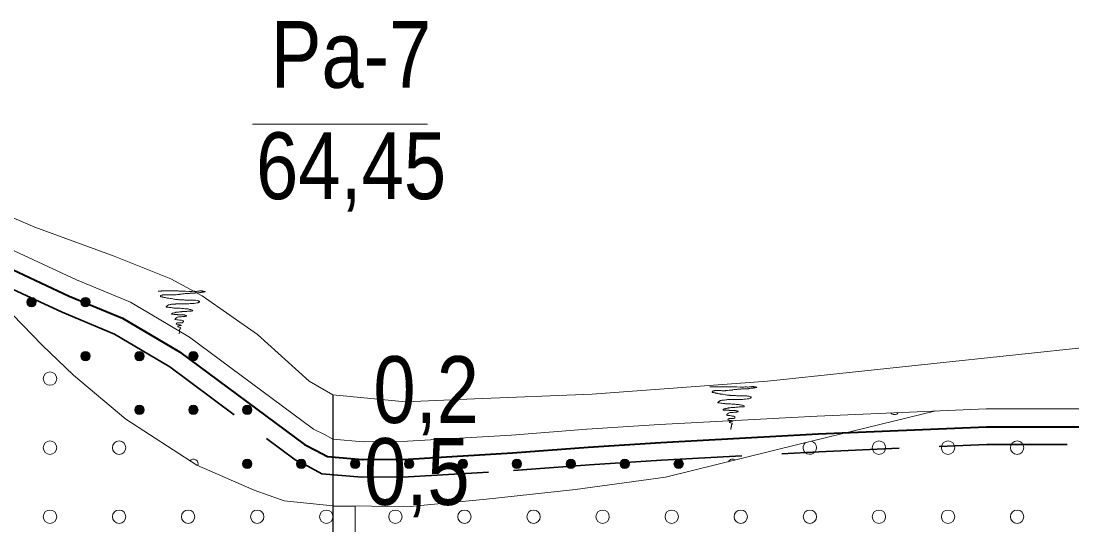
# Model space of a CAD drawing. Extents: x 640121 to 640955, y 6441885 to 6442246.
# Drawn here: x 640771.79 to 640818.96, y 6442150.81 to 6442173.44 of the extents above; entities that cross this region are included whole.
import ezdxf
from ezdxf.enums import TextEntityAlignment as Align

# ---------------------------------------------------------------- set-up
doc = ezdxf.new("R2010")
doc.units = 0
doc.header["$LTSCALE"] = 1.2
doc.linetypes.add('MEDIUM_DASHED', pattern=[4.5, 3, -1.5])
for name, color, linetype, lineweight in [('31', 7, 'Continuous', 13), ('32', 7, 'Continuous', 13), ('33', 7, 'Continuous', 13), ('35', 7, 'Continuous', 35), ('40', 7, 'Continuous', 13), ('43', 7, 'Continuous', 13), ('45', 7, 'Continuous', 13)]:
    doc.layers.add(name, color=color, linetype=linetype, lineweight=lineweight)

msp = doc.modelspace()

# ---------------------------------------------------------------- hatches: boundary and pattern name
at = {"layer": '45'}
for points in [[(640772.477, 6442160.814, 1), (640772.057, 6442160.814, 1)], [(640774.897, 6442160.814, 1), (640774.477, 6442160.814, 1)], [(640774.897, 6442158.394, 1), (640774.477, 6442158.394, 1)], [(640777.317, 6442158.394, 1), (640776.897, 6442158.394, 1)], [(640779.737, 6442158.394, 1), (640779.317, 6442158.394, 1)], [(640777.317, 6442155.974, 1), (640776.897, 6442155.974, 1)], [(640779.737, 6442155.974, 1), (640779.317, 6442155.974, 1)], [(640782.157, 6442155.974, 1), (640781.737, 6442155.974, 1)], [(640782.157, 6442153.554, 1), (640781.737, 6442153.554, 1)], [(640784.577, 6442153.554, 1), (640784.157, 6442153.554, 1)], [(640786.997, 6442153.554, 1), (640786.577, 6442153.554, 1)], [(640789.417, 6442153.554, 1), (640788.997, 6442153.554, 1)], [(640791.837, 6442153.554, 1), (640791.417, 6442153.554, 1)], [(640794.257, 6442153.554, 1), (640793.837, 6442153.554, 1)], [(640796.677, 6442153.554, 1), (640796.257, 6442153.554, 1)], [(640799.097, 6442153.554, 1), (640798.677, 6442153.554, 1)], [(640801.517, 6442153.554, 1), (640801.097, 6442153.554, 1)]]:
    msp.add_hatch(color=256, dxfattribs=at).paths.add_polyline_path(points)

# ---------------------------------------------------------------- linework, layer by layer
at = {"layer": '31'}
for points in [[(640766.27, 6442166.81), (640772.42, 6442164.18), (640775.97, 6442162.88), (640778.51, 6442161.86), (640779.92, 6442161.1), (640782.4, 6442159.37), (640784.73, 6442157.26), (640785.79, 6442156.66), (640789.05, 6442156.34), (640792.15, 6442156.48), (640797.43, 6442156.68), (640805.3, 6442157.27), (640819.95, 6442158.83), (640830.66, 6442159.34), (640843.85, 6442160.31), (640856.77, 6442160.63), (640864.53, 6442160.67), (640874.59, 6442160.86), (640880.68, 6442161.21), (640890.6, 6442162.23)], [(640766.2, 6442165.53), (640768.66, 6442162.89), (640770.97, 6442160.71), (640772.75, 6442158.89), (640774.15, 6442157.53), (640776.49, 6442155.56), (640779.68, 6442153.5), (640782.25, 6442152.37), (640783.6, 6442151.9), (640785.78, 6442151.67), (640789.26, 6442151.64), (640792.68, 6442151.97), (640796.68, 6442152.4), (640800.71, 6442152.95), (640806.66, 6442154.43), (640812.84, 6442155.93)], [(640771.49, 6442163.12), (640774.28, 6442161.82), (640776.71, 6442160.81), (640779.36, 6442159.25), (640784.92, 6442155.11), (640785.41, 6442154.87), (640785.78, 6442154.67), (640787.15, 6442154.55), (640789.13, 6442154.57), (640793.8, 6442154.85), (640797.19, 6442155.11), (640800.45, 6442155.32), (640807.52, 6442155.7), (640815.1, 6442156.02), (640823.55, 6442156.02), (640837.86, 6442156.27), (640859.29, 6442156.56), (640867.72, 6442156.02), (640874.73, 6442155.96), (640892.32, 6442157.59), (640908.53, 6442160.16), (640920.53, 6442162.05), (640928.43, 6442163.08), (640933.07, 6442163.64)]]:
    msp.add_lwpolyline(points, dxfattribs=at)
at = {"layer": '32'}
msp.add_line((640782.18, 6442168.81), (640790.04, 6442168.81), dxfattribs=at)
at = {"layer": '32', "lineweight": 25}
msp.add_line((640785.79, 6442156.66), (640785.79, 6442096.66), dxfattribs=at)
at = {"layer": '33'}
msp.add_lwpolyline([(640786.79, 6442131.66), (640786.79, 6442151.66), (640786.21, 6442151.66), (640785.79, 6442151.66), (640785.79, 6442131.66)], close=True, dxfattribs=at)
at = {"layer": '35', "lineweight": 40}
msp.add_lwpolyline([(640771.15, 6442162.4), (640773.96, 6442161.09), (640776.35, 6442160.1), (640778.91, 6442158.58), (640784.51, 6442154.42), (640785.04, 6442154.16), (640785.54, 6442153.88), (640787.12, 6442153.75), (640789.16, 6442153.77), (640793.85, 6442154.05), (640797.24, 6442154.31), (640800.5, 6442154.52), (640807.56, 6442154.9), (640815.12, 6442155.22), (640823.56, 6442155.22), (640837.88, 6442155.47), (640859.27, 6442155.76), (640867.7, 6442155.22), (640874.77, 6442155.16), (640892.41, 6442156.8), (640908.65, 6442159.37), (640919.89, 6442161.14)], dxfattribs=at)
at = {"layer": '35', "linetype": 'MEDIUM_DASHED'}
msp.add_lwpolyline([(640770.82, 6442161.67), (640773.64, 6442160.36), (640775.99, 6442159.38), (640778.47, 6442157.91), (640784.09, 6442153.73), (640784.67, 6442153.45), (640785.3, 6442153.1), (640787.09, 6442152.95), (640789.18, 6442152.97), (640793.9, 6442153.25), (640797.3, 6442153.51), (640800.54, 6442153.72), (640807.6, 6442154.1), (640815.14, 6442154.42), (640823.57, 6442154.42), (640837.89, 6442154.67), (640859.25, 6442154.96), (640867.67, 6442154.42), (640874.8, 6442154.36), (640892.51, 6442156), (640908.78, 6442158.58), (640919.09, 6442160.21)], dxfattribs=at)
at = {"layer": '40'}
for points in [[(640777.95, 6442161.31), (640777.98, 6442161.31), (640778.04, 6442161.31), (640778.09, 6442161.31), (640778.1, 6442161.32), (640778.16, 6442161.32), (640778.24, 6442161.32), (640778.4, 6442161.32), (640778.49, 6442161.32), (640778.51, 6442161.32), (640778.52, 6442161.32), (640778.56, 6442161.32), (640778.6, 6442161.32), (640778.66, 6442161.32), (640778.7, 6442161.32), (640778.73, 6442161.32), (640778.77, 6442161.32), (640778.81, 6442161.32), (640778.84, 6442161.32), (640778.88, 6442161.31), (640778.91, 6442161.31), (640778.94, 6442161.31), (640778.99, 6442161.31), (640779.16, 6442161.31), (640779.32, 6442161.3), (640779.36, 6442161.3), (640779.39, 6442161.3), (640779.41, 6442161.3), (640779.44, 6442161.3), (640779.47, 6442161.3), (640779.52, 6442161.31), (640779.54, 6442161.31), (640779.56, 6442161.31), (640779.57, 6442161.31), (640779.59, 6442161.31), (640779.63, 6442161.3), (640779.65, 6442161.3), (640779.67, 6442161.3), (640779.72, 6442161.31), (640779.75, 6442161.31), (640779.78, 6442161.31), (640779.8, 6442161.32), (640779.84, 6442161.32), (640779.86, 6442161.32), (640779.88, 6442161.32), (640779.9, 6442161.32), (640779.92, 6442161.32), (640779.94, 6442161.31), (640779.96, 6442161.31), (640779.98, 6442161.31)], [(640778.72, 6442161.15), (640778.7, 6442161.14), (640778.67, 6442161.14), (640778.66, 6442161.14), (640778.64, 6442161.14), (640778.62, 6442161.14), (640778.6, 6442161.14), (640778.57, 6442161.14), (640778.55, 6442161.14), (640778.51, 6442161.14), (640778.49, 6442161.14), (640778.46, 6442161.14), (640778.45, 6442161.14), (640778.43, 6442161.14), (640778.41, 6442161.14), (640778.39, 6442161.14), (640778.36, 6442161.14), (640778.33, 6442161.14), (640778.31, 6442161.14), (640778.29, 6442161.14), (640778.26, 6442161.14), (640778.24, 6442161.14), (640778.22, 6442161.14), (640778.2, 6442161.14), (640778.18, 6442161.14), (640778.15, 6442161.14), (640778.13, 6442161.13), (640778.11, 6442161.13), (640778.09, 6442161.12), (640778.08, 6442161.11), (640778.07, 6442161.11), (640778.06, 6442161.1), (640778.05, 6442161.08), (640778.06, 6442161.06), (640778.1, 6442161.05), (640778.13, 6442161.05), (640778.15, 6442161.04), (640778.18, 6442161.04), (640778.19, 6442161.04), (640778.21, 6442161.03), (640778.24, 6442161.03), (640778.26, 6442161.02), (640778.28, 6442161.02), (640778.31, 6442161.01), (640778.35, 6442161), (640778.39, 6442161), (640778.41, 6442160.99), (640778.43, 6442160.99), (640778.48, 6442160.98), (640778.53, 6442160.98)], [(640779.98, 6442161.31), (640780.01, 6442161.3), (640780.02, 6442161.3), (640780.05, 6442161.3), (640780.06, 6442161.29), (640780.05, 6442161.28), (640780.05, 6442161.29), (640780.04, 6442161.28), (640780.01, 6442161.28), (640779.98, 6442161.27), (640779.96, 6442161.27), (640779.94, 6442161.27), (640779.92, 6442161.26), (640779.9, 6442161.26), (640779.89, 6442161.25), (640779.86, 6442161.25), (640779.83, 6442161.25), (640779.81, 6442161.25), (640779.75, 6442161.24), (640779.72, 6442161.23), (640779.71, 6442161.23), (640779.68, 6442161.23), (640779.66, 6442161.23), (640779.64, 6442161.23), (640779.61, 6442161.22), (640779.59, 6442161.22), (640779.54, 6442161.22), (640779.51, 6442161.22), (640779.47, 6442161.22), (640779.43, 6442161.22), (640779.4, 6442161.22), (640779.38, 6442161.22), (640779.35, 6442161.21), (640779.32, 6442161.21), (640779.23, 6442161.21), (640779.21, 6442161.21), (640779.2, 6442161.2), (640779.16, 6442161.2), (640779.11, 6442161.19), (640779.07, 6442161.19), (640779.04, 6442161.19), (640779, 6442161.18), (640778.97, 6442161.18), (640778.94, 6442161.17), (640778.91, 6442161.17), (640778.9, 6442161.16), (640778.88, 6442161.16), (640778.85, 6442161.16), (640778.83, 6442161.16), (640778.81, 6442161.16), (640778.75, 6442161.15), (640778.72, 6442161.15)], [(640779.14, 6442160.74), (640779.09, 6442160.74), (640779.06, 6442160.74), (640779.02, 6442160.74), (640778.99, 6442160.74), (640778.96, 6442160.74), (640778.91, 6442160.74), (640778.87, 6442160.74), (640778.78, 6442160.74), (640778.74, 6442160.74), (640778.72, 6442160.73), (640778.67, 6442160.73), (640778.61, 6442160.72), (640778.55, 6442160.72), (640778.52, 6442160.71), (640778.49, 6442160.71), (640778.48, 6442160.71), (640778.46, 6442160.7), (640778.45, 6442160.7), (640778.43, 6442160.69), (640778.41, 6442160.69), (640778.4, 6442160.68), (640778.37, 6442160.66), (640778.35, 6442160.65), (640778.34, 6442160.63), (640778.33, 6442160.63), (640778.32, 6442160.62), (640778.31, 6442160.6), (640778.3, 6442160.59), (640778.31, 6442160.59), (640778.33, 6442160.59), (640778.36, 6442160.59), (640778.39, 6442160.59), (640778.44, 6442160.58), (640778.48, 6442160.57), (640778.53, 6442160.57), (640778.59, 6442160.56), (640778.62, 6442160.56), (640778.65, 6442160.55), (640778.68, 6442160.55), (640778.76, 6442160.55), (640778.83, 6442160.55), (640778.88, 6442160.54), (640778.94, 6442160.54), (640779.01, 6442160.53), (640779.08, 6442160.53), (640779.14, 6442160.51), (640779.18, 6442160.51), (640779.23, 6442160.51), (640779.27, 6442160.51)], [(640778.53, 6442160.98), (640778.6, 6442160.96), (640778.65, 6442160.95), (640778.68, 6442160.95), (640778.73, 6442160.94), (640778.78, 6442160.94), (640778.81, 6442160.93), (640778.84, 6442160.93), (640778.87, 6442160.92), (640778.91, 6442160.92), (640778.94, 6442160.92), (640778.98, 6442160.92), (640779.02, 6442160.92), (640779.06, 6442160.92), (640779.11, 6442160.92), (640779.15, 6442160.91), (640779.18, 6442160.91), (640779.2, 6442160.91), (640779.23, 6442160.91), (640779.27, 6442160.91), (640779.31, 6442160.91), (640779.36, 6442160.91), (640779.4, 6442160.91), (640779.43, 6442160.91), (640779.47, 6442160.91), (640779.49, 6442160.91), (640779.52, 6442160.91), (640779.55, 6442160.91), (640779.58, 6442160.9), (640779.61, 6442160.9), (640779.63, 6442160.9), (640779.7, 6442160.89), (640779.73, 6442160.88), (640779.76, 6442160.87), (640779.78, 6442160.86), (640779.8, 6442160.86), (640779.8, 6442160.84), (640779.8, 6442160.82), (640779.78, 6442160.81), (640779.77, 6442160.81), (640779.76, 6442160.8), (640779.74, 6442160.79), (640779.69, 6442160.78), (640779.62, 6442160.77), (640779.56, 6442160.76), (640779.52, 6442160.75), (640779.47, 6442160.75), (640779.43, 6442160.75), (640779.38, 6442160.75), (640779.32, 6442160.74), (640779.22, 6442160.74), (640779.14, 6442160.74)], [(640779.27, 6442160.51), (640779.3, 6442160.51), (640779.32, 6442160.5), (640779.36, 6442160.49), (640779.4, 6442160.48), (640779.42, 6442160.47), (640779.45, 6442160.47), (640779.48, 6442160.46), (640779.49, 6442160.45), (640779.5, 6442160.43), (640779.48, 6442160.42), (640779.47, 6442160.42), (640779.45, 6442160.41), (640779.39, 6442160.41), (640779.36, 6442160.41), (640779.35, 6442160.41), (640779.31, 6442160.41), (640779.27, 6442160.41), (640779.23, 6442160.4), (640779.2, 6442160.4), (640779.18, 6442160.4), (640779.11, 6442160.4), (640779.08, 6442160.39), (640779.06, 6442160.39), (640779.03, 6442160.39), (640779.01, 6442160.38), (640778.98, 6442160.38), (640778.94, 6442160.38), (640778.9, 6442160.38), (640778.86, 6442160.37), (640778.83, 6442160.36), (640778.81, 6442160.36), (640778.79, 6442160.36), (640778.77, 6442160.36), (640778.74, 6442160.36), (640778.73, 6442160.35), (640778.7, 6442160.34), (640778.69, 6442160.33), (640778.67, 6442160.33), (640778.65, 6442160.33), (640778.62, 6442160.32), (640778.59, 6442160.32), (640778.57, 6442160.3), (640778.55, 6442160.29), (640778.55, 6442160.27), (640778.57, 6442160.27), (640778.61, 6442160.27), (640778.66, 6442160.26), (640778.7, 6442160.26), (640778.72, 6442160.26), (640778.77, 6442160.26), (640778.8, 6442160.26)], [(640778.8, 6442160.26), (640778.81, 6442160.25), (640778.83, 6442160.25), (640778.86, 6442160.25), (640778.9, 6442160.25), (640778.91, 6442160.25), (640778.97, 6442160.24), (640779.01, 6442160.24), (640779.03, 6442160.24), (640779.05, 6442160.24), (640779.07, 6442160.24), (640779.1, 6442160.24), (640779.13, 6442160.24), (640779.15, 6442160.23), (640779.18, 6442160.22), (640779.2, 6442160.21), (640779.22, 6442160.21), (640779.22, 6442160.18), (640779.16, 6442160.17), (640779.08, 6442160.17), (640779.05, 6442160.17), (640779, 6442160.16), (640778.97, 6442160.16), (640778.93, 6442160.16), (640778.9, 6442160.15), (640778.86, 6442160.15), (640778.82, 6442160.14), (640778.78, 6442160.12), (640778.77, 6442160.11), (640778.75, 6442160.1), (640778.73, 6442160.09), (640778.72, 6442160.08), (640778.72, 6442160.06), (640778.7, 6442160.04), (640778.72, 6442160.03), (640778.74, 6442160.03), (640778.78, 6442160.02), (640778.84, 6442160.02), (640778.9, 6442160.01), (640778.93, 6442160), (640778.95, 6442160), (640778.99, 6442160), (640779.03, 6442159.99), (640779.08, 6442159.97), (640779.08, 6442159.95), (640779.07, 6442159.93), (640779.06, 6442159.92), (640779.03, 6442159.89), (640779.01, 6442159.88), (640778.98, 6442159.88), (640778.94, 6442159.88), (640778.9, 6442159.88), (640778.86, 6442159.88), (640778.82, 6442159.88), (640778.78, 6442159.87), (640778.77, 6442159.85), (640778.76, 6442159.84), (640778.77, 6442159.83), (640778.79, 6442159.82), (640778.85, 6442159.81), (640778.89, 6442159.8), (640778.91, 6442159.79), (640778.94, 6442159.79), (640778.97, 6442159.78), (640778.99, 6442159.77), (640778.98, 6442159.76), (640778.95, 6442159.76), (640778.91, 6442159.76), (640778.87, 6442159.75), (640778.85, 6442159.75), (640778.83, 6442159.75), (640778.83, 6442159.72), (640778.84, 6442159.71), (640778.85, 6442159.7), (640778.87, 6442159.69), (640778.9, 6442159.69), (640778.93, 6442159.68), (640778.95, 6442159.67), (640778.96, 6442159.65), (640778.94, 6442159.64), (640778.94, 6442159.62), (640778.93, 6442159.6), (640778.91, 6442159.59), (640778.91, 6442159.57), (640778.91, 6442159.54), (640778.91, 6442159.52), (640778.91, 6442159.51), (640778.91, 6442159.48), (640778.9, 6442159.47), (640778.9, 6442159.45), (640778.89, 6442159.43), (640778.89, 6442159.4), (640778.89, 6442159.4), (640778.89, 6442159.42)], [(640802.71, 6442157.01), (640802.74, 6442157.01), (640802.79, 6442157.01), (640802.85, 6442157.01), (640802.86, 6442157.02), (640802.91, 6442157.02), (640802.99, 6442157.02), (640803.15, 6442157.02), (640803.24, 6442157.02), (640803.26, 6442157.02), (640803.28, 6442157.02), (640803.32, 6442157.02), (640803.36, 6442157.02), (640803.41, 6442157.02), (640803.45, 6442157.02), (640803.48, 6442157.02), (640803.53, 6442157.02), (640803.56, 6442157.02), (640803.6, 6442157.02), (640803.64, 6442157.01), (640803.66, 6442157.01), (640803.7, 6442157.01), (640803.75, 6442157.01), (640803.92, 6442157.01), (640804.07, 6442157), (640804.12, 6442157), (640804.15, 6442157), (640804.17, 6442157), (640804.19, 6442157), (640804.23, 6442157), (640804.28, 6442157.01), (640804.3, 6442157.01), (640804.32, 6442157.01), (640804.33, 6442157.01), (640804.35, 6442157.01), (640804.38, 6442157), (640804.4, 6442157), (640804.43, 6442157), (640804.47, 6442157.01), (640804.5, 6442157.01), (640804.54, 6442157.01), (640804.56, 6442157.02), (640804.59, 6442157.02), (640804.61, 6442157.03), (640804.64, 6442157.03), (640804.66, 6442157.03), (640804.68, 6442157.02), (640804.7, 6442157.01), (640804.72, 6442157.01), (640804.74, 6442157.01)], [(640803.48, 6442156.85), (640803.46, 6442156.85), (640803.43, 6442156.85), (640803.41, 6442156.84), (640803.39, 6442156.84), (640803.38, 6442156.84), (640803.35, 6442156.84), (640803.33, 6442156.84), (640803.3, 6442156.84), (640803.27, 6442156.84), (640803.25, 6442156.84), (640803.22, 6442156.85), (640803.2, 6442156.85), (640803.18, 6442156.85), (640803.17, 6442156.85), (640803.14, 6442156.85), (640803.12, 6442156.85), (640803.08, 6442156.85), (640803.06, 6442156.85), (640803.05, 6442156.85), (640803.02, 6442156.85), (640803, 6442156.85), (640802.97, 6442156.85), (640802.96, 6442156.85), (640802.93, 6442156.85), (640802.91, 6442156.84), (640802.89, 6442156.83), (640802.87, 6442156.83), (640802.85, 6442156.82), (640802.84, 6442156.82), (640802.82, 6442156.81), (640802.81, 6442156.8), (640802.81, 6442156.78), (640802.81, 6442156.76), (640802.86, 6442156.76), (640802.89, 6442156.76), (640802.91, 6442156.74), (640802.93, 6442156.74), (640802.95, 6442156.74), (640802.96, 6442156.73), (640802.99, 6442156.73), (640803.02, 6442156.73), (640803.03, 6442156.72), (640803.07, 6442156.71), (640803.11, 6442156.7), (640803.14, 6442156.7), (640803.17, 6442156.7), (640803.19, 6442156.69), (640803.23, 6442156.68), (640803.29, 6442156.68)], [(640804.74, 6442157.01), (640804.76, 6442157), (640804.78, 6442157), (640804.8, 6442157), (640804.82, 6442156.99), (640804.8, 6442156.98), (640804.81, 6442156.99), (640804.79, 6442156.98), (640804.77, 6442156.98), (640804.74, 6442156.97), (640804.72, 6442156.97), (640804.7, 6442156.97), (640804.68, 6442156.97), (640804.66, 6442156.97), (640804.65, 6442156.95), (640804.62, 6442156.95), (640804.58, 6442156.95), (640804.56, 6442156.95), (640804.5, 6442156.94), (640804.48, 6442156.94), (640804.46, 6442156.94), (640804.44, 6442156.93), (640804.41, 6442156.93), (640804.4, 6442156.93), (640804.37, 6442156.92), (640804.35, 6442156.92), (640804.29, 6442156.92), (640804.26, 6442156.92), (640804.23, 6442156.92), (640804.19, 6442156.92), (640804.16, 6442156.92), (640804.13, 6442156.92), (640804.1, 6442156.91), (640804.07, 6442156.91), (640803.99, 6442156.91), (640803.97, 6442156.91), (640803.95, 6442156.91), (640803.92, 6442156.9), (640803.87, 6442156.89), (640803.83, 6442156.89), (640803.8, 6442156.89), (640803.75, 6442156.88), (640803.72, 6442156.88), (640803.7, 6442156.87), (640803.67, 6442156.87), (640803.66, 6442156.86), (640803.64, 6442156.86), (640803.61, 6442156.86), (640803.59, 6442156.86), (640803.57, 6442156.86), (640803.5, 6442156.85), (640803.48, 6442156.85)], [(640803.89, 6442156.44), (640803.85, 6442156.44), (640803.81, 6442156.44), (640803.77, 6442156.44), (640803.74, 6442156.44), (640803.71, 6442156.44), (640803.67, 6442156.44), (640803.63, 6442156.44), (640803.54, 6442156.44), (640803.5, 6442156.44), (640803.47, 6442156.43), (640803.43, 6442156.43), (640803.37, 6442156.42), (640803.3, 6442156.42), (640803.28, 6442156.41), (640803.25, 6442156.41), (640803.24, 6442156.41), (640803.22, 6442156.4), (640803.2, 6442156.4), (640803.18, 6442156.4), (640803.17, 6442156.39), (640803.15, 6442156.38), (640803.12, 6442156.36), (640803.11, 6442156.35), (640803.1, 6442156.34), (640803.08, 6442156.33), (640803.08, 6442156.32), (640803.06, 6442156.31), (640803.06, 6442156.29), (640803.07, 6442156.29), (640803.09, 6442156.29), (640803.12, 6442156.29), (640803.14, 6442156.29), (640803.2, 6442156.28), (640803.24, 6442156.28), (640803.29, 6442156.27), (640803.35, 6442156.26), (640803.38, 6442156.26), (640803.41, 6442156.25), (640803.44, 6442156.25), (640803.52, 6442156.25), (640803.59, 6442156.25), (640803.64, 6442156.25), (640803.69, 6442156.24), (640803.77, 6442156.23), (640803.84, 6442156.23), (640803.9, 6442156.22), (640803.94, 6442156.22), (640803.99, 6442156.22), (640804.03, 6442156.21)], [(640803.29, 6442156.68), (640803.36, 6442156.67), (640803.41, 6442156.65), (640803.44, 6442156.65), (640803.48, 6442156.64), (640803.53, 6442156.64), (640803.57, 6442156.64), (640803.6, 6442156.64), (640803.62, 6442156.62), (640803.66, 6442156.62), (640803.69, 6442156.62), (640803.74, 6442156.62), (640803.78, 6442156.62), (640803.81, 6442156.62), (640803.86, 6442156.62), (640803.9, 6442156.61), (640803.93, 6442156.61), (640803.95, 6442156.61), (640803.99, 6442156.61), (640804.02, 6442156.61), (640804.07, 6442156.61), (640804.11, 6442156.61), (640804.16, 6442156.61), (640804.19, 6442156.61), (640804.23, 6442156.61), (640804.25, 6442156.61), (640804.28, 6442156.61), (640804.31, 6442156.61), (640804.34, 6442156.61), (640804.37, 6442156.61), (640804.39, 6442156.6), (640804.46, 6442156.59), (640804.49, 6442156.58), (640804.52, 6442156.57), (640804.54, 6442156.56), (640804.56, 6442156.56), (640804.56, 6442156.54), (640804.55, 6442156.52), (640804.54, 6442156.52), (640804.53, 6442156.51), (640804.52, 6442156.5), (640804.49, 6442156.49), (640804.45, 6442156.48), (640804.38, 6442156.47), (640804.31, 6442156.46), (640804.28, 6442156.46), (640804.23, 6442156.46), (640804.19, 6442156.45), (640804.14, 6442156.45), (640804.07, 6442156.44), (640803.98, 6442156.44), (640803.89, 6442156.44)], [(640804.03, 6442156.21), (640804.05, 6442156.21), (640804.08, 6442156.2), (640804.12, 6442156.19), (640804.16, 6442156.19), (640804.18, 6442156.17), (640804.2, 6442156.17), (640804.23, 6442156.16), (640804.25, 6442156.16), (640804.25, 6442156.13), (640804.24, 6442156.13), (640804.23, 6442156.12), (640804.21, 6442156.11), (640804.15, 6442156.11), (640804.12, 6442156.11), (640804.1, 6442156.11), (640804.07, 6442156.11), (640804.02, 6442156.11), (640803.98, 6442156.1), (640803.96, 6442156.1), (640803.93, 6442156.1), (640803.87, 6442156.1), (640803.83, 6442156.09), (640803.81, 6442156.09), (640803.78, 6442156.09), (640803.77, 6442156.08), (640803.74, 6442156.08), (640803.69, 6442156.08), (640803.66, 6442156.08), (640803.62, 6442156.07), (640803.59, 6442156.07), (640803.57, 6442156.07), (640803.54, 6442156.07), (640803.53, 6442156.06), (640803.5, 6442156.06), (640803.49, 6442156.05), (640803.46, 6442156.04), (640803.45, 6442156.04), (640803.43, 6442156.04), (640803.41, 6442156.03), (640803.38, 6442156.02), (640803.35, 6442156.02), (640803.32, 6442156.01), (640803.31, 6442155.99), (640803.31, 6442155.97), (640803.33, 6442155.97), (640803.36, 6442155.97), (640803.41, 6442155.96), (640803.45, 6442155.96), (640803.48, 6442155.96), (640803.53, 6442155.96), (640803.56, 6442155.96)], [(640803.56, 6442155.96), (640803.57, 6442155.95), (640803.59, 6442155.95), (640803.62, 6442155.95), (640803.65, 6442155.95), (640803.67, 6442155.95), (640803.72, 6442155.95), (640803.77, 6442155.95), (640803.78, 6442155.95), (640803.81, 6442155.95), (640803.83, 6442155.95), (640803.86, 6442155.95), (640803.89, 6442155.94), (640803.91, 6442155.93), (640803.93, 6442155.92), (640803.96, 6442155.92), (640803.98, 6442155.91), (640803.98, 6442155.89), (640803.92, 6442155.87), (640803.84, 6442155.87), (640803.81, 6442155.87), (640803.75, 6442155.86), (640803.72, 6442155.86), (640803.69, 6442155.86), (640803.65, 6442155.86), (640803.62, 6442155.86), (640803.58, 6442155.84), (640803.54, 6442155.83), (640803.53, 6442155.81), (640803.5, 6442155.8), (640803.49, 6442155.79), (640803.48, 6442155.78), (640803.47, 6442155.76), (640803.46, 6442155.74), (640803.47, 6442155.74), (640803.5, 6442155.73), (640803.53, 6442155.72), (640803.6, 6442155.72), (640803.65, 6442155.71), (640803.68, 6442155.71), (640803.71, 6442155.7), (640803.74, 6442155.7), (640803.78, 6442155.69), (640803.83, 6442155.68), (640803.83, 6442155.65), (640803.83, 6442155.63), (640803.82, 6442155.62), (640803.78, 6442155.59), (640803.77, 6442155.59), (640803.74, 6442155.59), (640803.69, 6442155.59), (640803.65, 6442155.59), (640803.62, 6442155.59), (640803.57, 6442155.59), (640803.53, 6442155.57), (640803.53, 6442155.56), (640803.52, 6442155.54), (640803.53, 6442155.53), (640803.54, 6442155.53), (640803.6, 6442155.51), (640803.65, 6442155.5), (640803.67, 6442155.5), (640803.7, 6442155.49), (640803.73, 6442155.48), (640803.75, 6442155.47), (640803.74, 6442155.47), (640803.71, 6442155.47), (640803.67, 6442155.46), (640803.62, 6442155.45), (640803.6, 6442155.45), (640803.59, 6442155.45), (640803.59, 6442155.42), (640803.6, 6442155.41), (640803.61, 6442155.41), (640803.63, 6442155.39), (640803.65, 6442155.39), (640803.68, 6442155.38), (640803.71, 6442155.38), (640803.71, 6442155.35), (640803.7, 6442155.34), (640803.69, 6442155.32), (640803.68, 6442155.3), (640803.67, 6442155.29), (640803.67, 6442155.27), (640803.67, 6442155.24), (640803.67, 6442155.23), (640803.66, 6442155.21), (640803.66, 6442155.18), (640803.66, 6442155.17), (640803.65, 6442155.15), (640803.65, 6442155.13), (640803.65, 6442155.11), (640803.65, 6442155.1), (640803.65, 6442155.12)]]:
    msp.add_lwpolyline(points, dxfattribs=at)
at = {"layer": '43'}
for centre in [(640773.094, 6442157.381), (640773.094, 6442154.281), (640776.194, 6442154.281), (640810.294, 6442154.281), (640813.394, 6442154.281), (640816.494, 6442154.281), (640773.094, 6442151.181), (640776.194, 6442151.181), (640779.294, 6442151.181), (640782.394, 6442151.181), (640785.494, 6442151.181), (640788.594, 6442151.181), (640791.694, 6442151.181), (640794.794, 6442151.181), (640797.894, 6442151.181), (640800.994, 6442151.181), (640804.094, 6442151.181), (640807.194, 6442151.181), (640810.294, 6442151.181), (640813.394, 6442151.181), (640816.494, 6442151.181)]:
    msp.add_circle(centre, 0.3, dxfattribs=at)
msp.add_arc((640807.194, 6442154.281), 0.3, 130.2169, 77.1024, dxfattribs=at)
at = {"layer": '45'}
for centre in [(640772.267, 6442160.814), (640774.687, 6442160.814), (640774.687, 6442158.394), (640777.107, 6442158.394), (640779.527, 6442158.394), (640777.107, 6442155.974), (640779.527, 6442155.974), (640781.947, 6442155.974), (640781.947, 6442153.554), (640784.367, 6442153.554), (640786.787, 6442153.554), (640789.207, 6442153.554), (640791.627, 6442153.554), (640794.047, 6442153.554), (640796.467, 6442153.554), (640798.887, 6442153.554), (640801.307, 6442153.554)]:
    msp.add_circle(centre, 0.21, dxfattribs=at)
for centre, start, end in [((640777.107, 6442160.814), 223.8688, 254.894), ((640810.987, 6442155.974), 218.8444, 326.0379), ((640779.527, 6442153.554), 338.9845, 137.1749), ((640803.727, 6442153.554), 55.7824, 152.1341)]:
    msp.add_arc(centre, 0.21, start, end, dxfattribs=at)

# ---------------------------------------------------------------- texts
at = {"layer": '32', "width": 0.85}
for s, p in [('Pa-7', (640786.605, 6442170.44)), ('64,45', (640786.605, 6442165.44)), ('0,2', (640789.975, 6442155.39)), ('0,5', (640789.555, 6442151.71))]:
    msp.add_text(s, height=3, dxfattribs=at).set_placement(p, align=Align.CENTER)

doc.saveas('drawing.dxf')
